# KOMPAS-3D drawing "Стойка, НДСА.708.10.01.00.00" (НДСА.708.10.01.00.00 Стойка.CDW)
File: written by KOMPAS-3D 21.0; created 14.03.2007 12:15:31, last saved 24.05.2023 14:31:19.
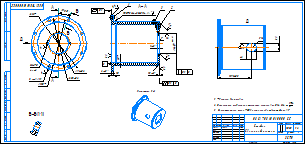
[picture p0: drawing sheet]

Sheet 1: A4x3, landscape

Document properties: Полное имя файла: НДСА.708.10.01.00.00 Стойка.a3d; Автор: Ширяева О.А.; Организация: Эсто-вакуум; Форматы листов документа: A4@4~3; Масса: 10.550806; PDM_DOCXDTO: <item xmlns="http://appius.ru/pdm" xmlns:xs="http://www.w3.org/2001/XMLSchema" xmlns:xsi="http://www.w3.org/2001/XMLSchema-instance" xsi:type="item">  <element xmlns:d2p1="http://v8.1c.ru/8.1/data/enterprise/current-config" xsi:type="d2p1:CatalogRef.aps_Элемен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; PDM_ITEMXDTO: <item xmlns="http://appius.ru/pdm" xmlns:xs="http://www.w3.org/2001/XMLSchema" xmlns:xsi="http://www.w3.org/2001/XMLSchema-instance" xsi:type="item">  <element xmlns:d2p1="http://v8.1c.ru/8.1/data/enterprise/current-config" xsi:type="d2p1:CatalogRef.aps_Элемен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; PDM_DRAWINGXDTO: <item xmlns="http://appius.ru/pdm" xmlns:xs="http://www.w3.org/2001/XMLSchema" xmlns:xsi="http://www.w3.org/2001/XMLSchema-instance" xsi:type="item">  <element xmlns:d2p1="http://v8.1c.ru/8.1/data/enterprise/current-config" xsi:type="d2p1:CatalogRef.aps_Элемен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; PLM_CDWXDTO: <item xmlns="http://appius.ru/pdm" xmlns:xs="http://www.w3.org/2001/XMLSchema" xmlns:xsi="http://www.w3.org/2001/XMLSchema-instance" xsi:type="item">  <element xmlns:d2p1="http://v8.1c.ru/8.1/data/enterprise/current-config" xsi:type="d2p1:CatalogRef.aps_Элемен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

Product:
- Part/product: Стойка  | designation НДСА.708.10.01.00.00
    Масса: 10.550806
    additional columns: <item xmlns="http://appius.ru/pdm" xmlns:xs="http://www.w3.org/2001/XMLSchema" x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; <item xmlns="http://appius.ru/pdm" xmlns:xs="http://www.w3.org/2001/XMLSchema" x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; <item xmlns="http://appius.ru/pdm" xmlns:xs="http://www.w3.org/2001/XMLSchema" x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
  - Component [detail]: Шов сварной 1 (стойка)  | qty 2  | Материал: Сталь 20  ГОСТ 1050-88 (density 7820 kg/m3); Масса: 0.054253; additional columns: <item xmlns="http://appius.ru/pdm" xmlns:xs="http://www.w3.org/2001/XMLSchema" x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; <item xmlns="http://appius.ru/pdm" xmlns:xs="http://www.w3.org/2001/XMLSchema" x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; source file: Шов сварной 1 (стойка).m3d
  - Component [detail]: Фланец верхний  | designation НДСА.014.01.09.01.03  | pos. 3  | Материал: Сталь 20  ГОСТ 1050-88 (density 7820 kg/m3); Масса: 1.270585; Форматы листов документа: A4; additional columns: <item xmlns="http://appius.ru/pdm" xmlns:xs="http://www.w3.org/2001/XMLSchema" x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; <item xmlns="http://appius.ru/pdm" xmlns:xs="http://www.w3.org/2001/XMLSchema" x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; <item xmlns="http://appius.ru/pdm" xmlns:xs="http://www.w3.org/2001/XMLSchema" x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; <item xmlns="http://appius.ru/pdm" xmlns:xs="http://www.w3.org/2001/XMLSchema" x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; <item xmlns="http://appius.ru/pdm" xmlns:xs="http://www.w3.org/2001/XMLSchema" x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; <item xmlns="http://appius.ru/pdm" xmlns:xs="http://www.w3.org/2001/XMLSchema" x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; source file: НДСА.014.01.09.01.03 Фланец верхний.CDW, НДСА.014.01.09.01.03 Фланец верхний.m3d
  - Component [detail]: Труба  | designation НДСА.708.10.01.00.01  | pos. 1  | Материал: Труба$d180х10 ГОСТ 8732-78;20 ГОСТ 8731-74$ (density 7859 kg/m3); Масса: 7.249004; additional columns: <item xmlns="http://appius.ru/pdm" xmlns:xs="http://www.w3.org/2001/XMLSchema" x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; <item xmlns="http://appius.ru/pdm" xmlns:xs="http://www.w3.org/2001/XMLSchema" x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; <item xmlns="http://appius.ru/pdm" xmlns:xs="http://www.w3.org/2001/XMLSchema" x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; source file: НДСА.708.10.01.00.01 Труба.CDW, НДСА.708.10.01.00.01 Труба.m3d
  - Component [detail]: Фланец нижний  | designation НДСА.014.01.09.01.01  | pos. 2  | Материал: Сталь 20 ГОСТ 1050-88 (density 7859 kg/m3); Масса: 1.922711; Форматы листов документа: A4; additional columns: <item xmlns="http://appius.ru/pdm" xmlns:xs="http://www.w3.org/2001/XMLSchema" x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; <item xmlns="http://appius.ru/pdm" xmlns:xs="http://www.w3.org/2001/XMLSchema" x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; <item xmlns="http://appius.ru/pdm" xmlns:xs="http://www.w3.org/2001/XMLSchema" x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; <item xmlns="http://appius.ru/pdm" xmlns:xs="http://www.w3.org/2001/XMLSchema" x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; <item xmlns="http://appius.ru/pdm" xmlns:xs="http://www.w3.org/2001/XMLSchema" x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; <item xmlns="http://appius.ru/pdm" xmlns:xs="http://www.w3.org/2001/XMLSchema" x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; source file: НДСА.014.01.09.01.01 Фланец нижний.CDW, НДСА.014.01.09.01.01 Фланец нижний.m3d

Title block, sheet 1: Наименование: Стойка / Сборочный чертеж; Масса: 10,55; scale: 1:2; Количество листов документа: 1; organisation: ЭСТО; Форматы листов документа: A4 3; stored path: D:\Шлейф\УКРД.762.10.00.00.00 Верхняя стойка\УКРД.762.10.01.00.00 СБ Стойка.cdw; Разработал: Волкова; Разработал, date: 17.01.2020

Views: Разрез А-А, Разрез Б-Б, Вид по стрелке 6
Referenced files in E:\НДСА.014.01.09.00.00 Верхняя стойка гидроподъемника\: Шов сварной 1 (стойка).m3d, НДСА.014.01.09.01.03 Фланец верхний.m3d, НДСА.014.01.09.01.02 Труба.m3d
Referenced files in C:\Users\s.pischagina\Desktop\PLM\: НДСА.014.01.09.01.01 Фланец нижний.m3d, НДСА.708.10.01.00.00 Стойка.a3d, НДСА.708.10.01.00.01 Труба.m3d, Шов сварной 1 (стойка).m3d, НДСА.014.01.09.01.03 Фланец верхний.m3d
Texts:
  ГОСТ 5264-80-С11- 6,3
  НДСА.708.10.01.00.00
  Фланец нижний
  НДСА.014.01.09.01.01
  НДСА.014.01.09.01.01 Фланец нижний
  Труба
  НДСА.708.10.01.00.01
  НДСА.708.10.01.00.01 Труба
  Шов сварной 1 (стойка)
  Фланец верхний
  НДСА.014.01.09.01.03
  НДСА.014.01.09.01.03 Фланец верхний
  НДСА.708.10.01.00.00 Стойка
Dimensions and other numbers on the sheet: 10; 3,2; 0,1; 84; 1; 2; 6,3; 1,5; 3; 1,6; 42; 32; 16; 139,5±0,5; 7; 1:2; 10,55; 17.01.2020

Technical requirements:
  * Размеры для справок.
  Неуказанные предельные отклонения размеров по H14, h14,    IT14 2 .
  Покрытие эмаль серая, 7001, кроме резьб. отверстий и пов. Г.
